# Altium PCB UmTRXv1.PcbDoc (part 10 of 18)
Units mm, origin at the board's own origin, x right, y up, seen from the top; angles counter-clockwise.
Board outline 172 x 113 mm, 6 copper layers (Top Layer, GND, MidLayer1, Mid-Layer 2, InternalPlane2, Bottom Layer); 766 components, 613 nets, 3008 pads, 1360 vias.
Unrouted connection lines stored in the file: 2.
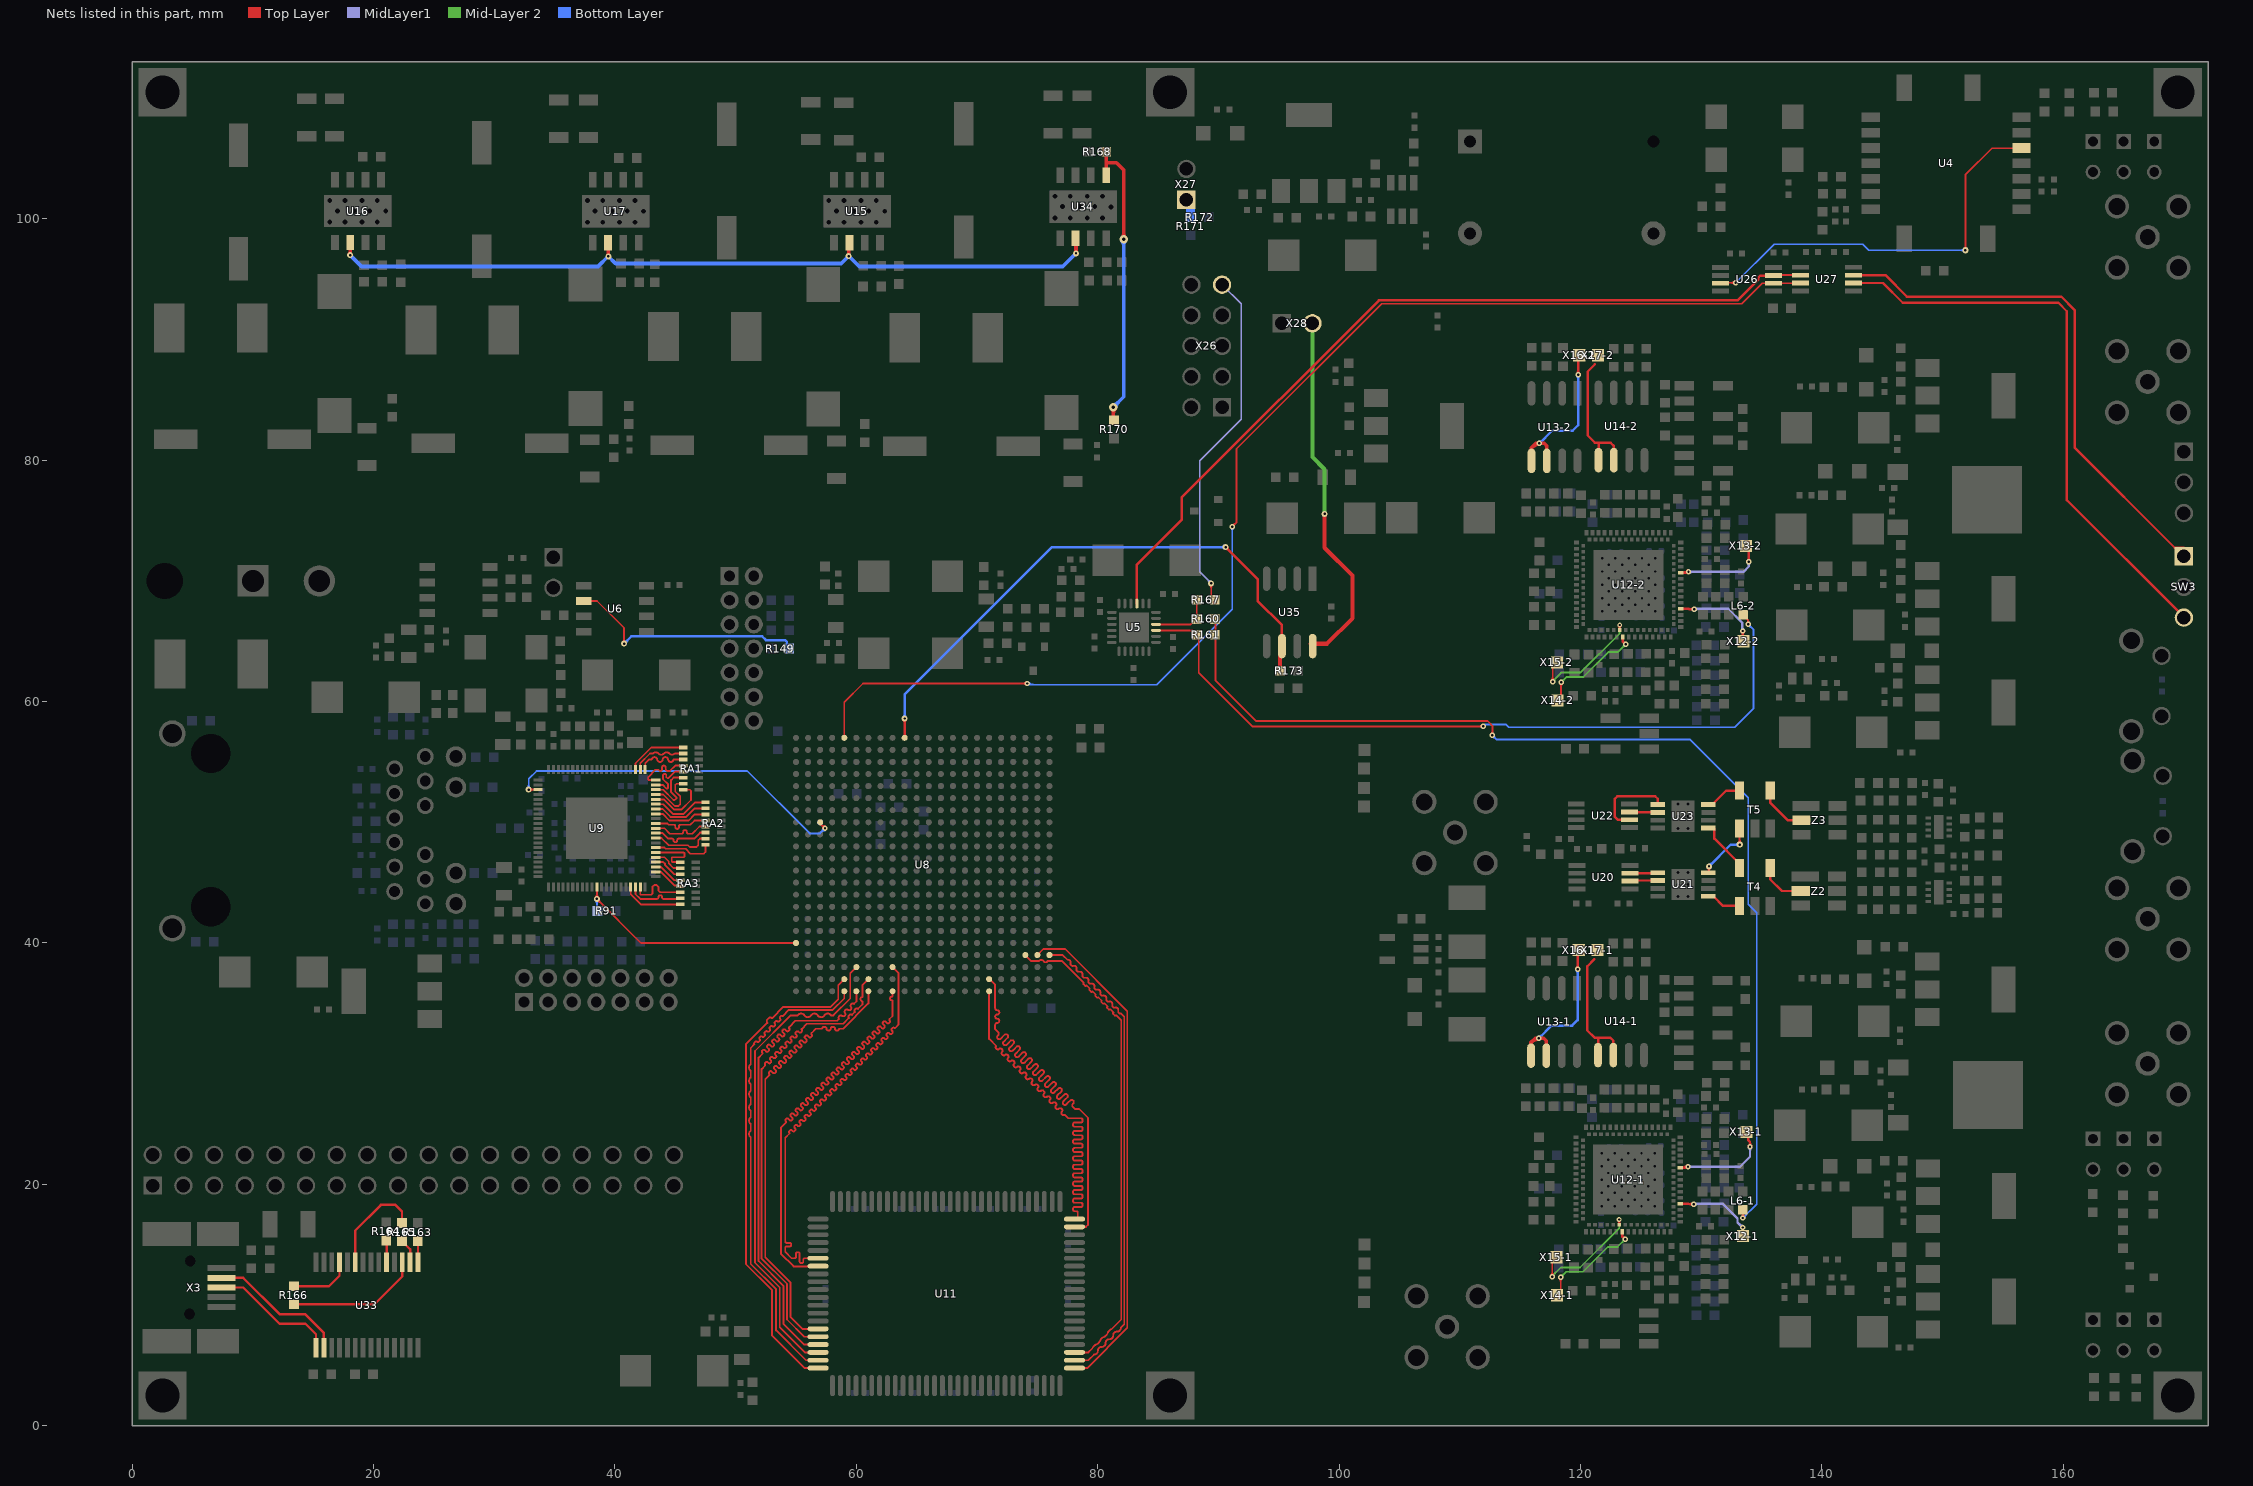
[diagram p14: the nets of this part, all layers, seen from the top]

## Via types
v1: diameter 0.45, hole 0.2, Top Layer to Bottom Layer, tented both sides, 554 vias
v2: diameter 0.5, hole 0.2, Top Layer to Bottom Layer, tented both sides, 468 vias
v3: diameter 0.7, hole 0.3, Top Layer to Bottom Layer, tented both sides, 206 vias
v4: diameter 0.4, hole 0.2, Top Layer to Bottom Layer, tented both sides, 82 vias
v5: diameter 0.8, hole 0.3, Top Layer to Bottom Layer, tented both sides, 16 vias
v6: diameter 0.6, hole 0.25, Top Layer to Bottom Layer, tented both sides, 16 vias
v7: diameter 0.5, hole 0.3, Top Layer to Bottom Layer, tented both sides, 8 vias
v8: diameter 0.7, hole 0.3, Top Layer to Bottom Layer, 4 vias
v9: diameter 0.6, hole 0.3, Top Layer to Bottom Layer, tented both sides, 4 vias
v10: diameter 0.5, hole 0.2, Top Layer to Bottom Layer, 2 vias

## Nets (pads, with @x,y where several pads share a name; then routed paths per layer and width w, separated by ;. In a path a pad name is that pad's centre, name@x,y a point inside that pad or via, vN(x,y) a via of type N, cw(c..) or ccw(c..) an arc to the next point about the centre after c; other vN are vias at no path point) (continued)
NetR149_2: R149.2 U6.2 | length 21.3
  Top Layer w0.15: U6.2@37.401,68.339 38.511,68.339 40.75,66.1 v2(40.75,64.8) ; v2@40.626,64.924 ccw(c40.328,65.222) 40.75,65.222 ccw(c41.172,65.222) v2@40.874,64.924
  Bottom Layer w0.2: v2(40.75,64.8) 41.35,65.4 52.2,65.4 52.5,65.1 54.1,65.1 54.25,64.95 R149.2@54.25,64.4 ; v2@40.75,64.95 ccw(c40.75,65.312) 41.006,65.056 ccw(c41.262,64.8) v2@40.9,64.8
NetR160_1: R160.1 R167.1 U5.22 | length 5.1
  Top Layer w0.15: U5.22@84.825,66.4 87.7,66.4 88.2,66.9 R167.1@88.2,68.45
NetR163_2: R163.2 U33.1 | length 1.8
  Top Layer w0.2: R163.2@23.65,15.3 23.675,15.275 U33.1@23.675,13.55
NetR164_2: R164.2 U33.5 | length 1.8
  Top Layer w0.2: R164.2@21.05,15.35 21.075,15.325 U33.5@21.075,13.55
NetR165_1: R165.1 U33.2 | length 2
  Top Layer w0.2: R165.1@22.35,15.3 23.025,14.625 U33.2@23.025,13.55
NetR165_2: R165.2 U33.9 | length 8.6
  Top Layer w0.2: U33.9@18.475,13.55 18.475,16.175 20.6,18.3 21.8,18.3 22.35,17.75 R165.2@22.35,16.8
NetR166_1: R166.1 U33.3 | length 11.1
  Top Layer w0.2: R166.1@13.4,10.05 20.05,10.05 22.375,12.375 U33.3@22.375,13.55
NetR166_2: R166.2 U33.11 | length 5.3
  Top Layer w0.2: R166.2@13.4,11.55 16.3,11.55 17.175,12.425 U33.11@17.175,13.55
NetR168_2: R168.2 R170.2 U34.5 | length 27.8
  Top Layer w0.3: U34.5@80.703,103.602 80.703,104.65 ; R168.2@80.703,105.547 80.703,104.65 ; v3@81.159,84.259 cw(c80.817,83.917) 81.3,83.917 cw(c81.783,83.917) v3@81.441,84.259 ; v3(81.3,84.4) 81.3,83.35 R170.2@81.35,83.3 ; v3@82.009,98.441 ccw(c81.667,98.783) 82.15,98.783 ccw(c82.633,98.783) v3@82.291,98.441 ; v3(82.15,98.3) 82.15,104.05 81.55,104.65 80.703,104.65
  Bottom Layer w0.3: v3(81.3,84.4) 82.15,85.25 v3(82.15,98.3) ; v3@81.3,84.6 ccw(c81.3,85.083) 81.641,84.741 ccw(c81.983,84.4) v3@81.5,84.4 ; v3@82.009,98.159 cw(c81.667,97.817) 82.15,97.817 cw(c82.633,97.817) v3@82.291,98.159
NetR171_2: R171.2 R172.2 X27.1 | length 1.6
  Bottom Layer w0.75: X27.1@87.35,101.6 87.7,101.25 R172.2@87.7,100.15
NetRA1_1: RA1.1 U9.3 | length 5
  Top Layer w0.15: U9.3@41.7,54.375 41.7,54.9 43,56.2 RA1.1@45.65,56.2
NetRA1_2: RA1.2 U9.2 | length 4.6
  Top Layer w0.15: U9.2@42.1,54.375 42.1,54.9 42.9,55.7 43.15,55.7 cw(c43.375,55.497) 43.6,55.7 ccw(c43.825,55.903) 44.05,55.7 cw(c44.275,55.497) 44.5,55.7 ccw(c44.725,55.903) 44.95,55.7 RA1.2@45.65,55.7
NetRA1_3: RA1.3 U9.1 | length 4.6
  Top Layer w0.15: U9.1@42.5,54.375 42.5,54.9 42.8,55.2 43.05,55.2 cw(c43.275,55.173) 43.5,55.2 ccw(c43.725,55.227) 43.95,55.2 cw(c44.175,55.173) 44.4,55.2 ccw(c44.625,55.227) 44.85,55.2 RA1.3@45.65,55.2
NetRA1_4: RA1.4 U9.84 | length 4.9
  Top Layer w0.15: U9.84@43.375,53.5 42.8,53.5 42.75,53.55 42.75,53.75 43.35,54.35 43.604,54.35 43.704,54.25 43.75,54.25 ccw(c43.75,54.4) 43.9,54.4 43.9,54.547 cw(c44.05,54.547) 44.05,54.697 cw(c44.05,54.547) 44.2,54.547 44.2,54.4 ccw(c44.35,54.4) 44.35,54.25 44.55,54.25 45,54.7 RA1.4@45.65,54.7
NetRA1_5: RA1.5 U9.83 | length 4.6
  Top Layer w0.15: U9.83@43.375,53.1 43.95,53.1 44.25,52.8 44.35,52.8 44.4,52.85 44.4,53.15 43.975,53.575 43.975,53.925 44.05,54 44.2,54 44.25,53.95 44.25,53.75 44.35,53.65 44.4,53.65 44.95,54.2 RA1.5@45.65,54.2
NetRA1_6: RA1.6 U9.82 | length 4.9
  Top Layer w0.15: U9.82@43.375,52.7 43.996,52.7 44.846,51.85 44.95,51.85 45.1,52 45.1,52.05 44.65,52.5 44.65,53.5 44.85,53.7 RA1.6@45.65,53.7
NetRA1_7: RA1.7 U9.81 | length 4.9
  Top Layer w0.15: U9.81@43.375,52.3 44.004,52.3 44.954,51.35 45.25,51.35 45.4,51.5 45.4,52.15 45,52.55 45,53.1 45.1,53.2 RA1.7@45.65,53.2
NetRA1_8: RA1.8 U9.80 | length 5
  Top Layer w0.15: U9.80@43.375,51.9 44.05,51.9 44.9,51.05 45.5,51.05 46.3,51.85 46.3,52.6 46.2,52.7 RA1.8@45.65,52.7
NetRA2_1: RA2.1 U9.79 | length 4.8
  Top Layer w0.15: U9.79@43.375,51.5 44,51.5 44.8,50.7 45.7,50.7 46.65,51.65 RA2.1@47.5,51.65
NetRA2_2: RA2.2 U9.78 | length 4.7
  Top Layer w0.15: U9.78@43.375,51.1 43.95,51.1 44.6,50.45 45.9,50.45 46.6,51.15 RA2.2@47.5,51.15
NetRA2_3: RA2.3 U9.77 | length 4.6
  Top Layer w0.15: U9.77@43.375,50.7 43.95,50.7 44.5,50.15 46.1,50.15 46.6,50.65 RA2.3@47.5,50.65
NetRA2_4: RA2.4 U9.75 | length 4.8
  Top Layer w0.15: U9.75@43.375,49.9 44.35,49.9 44.45,49.8 44.865,49.8 cw(c44.865,49.665) 45,49.665 45,49.587 ccw(c45.135,49.587) 45.135,49.452 45.165,49.452 ccw(c45.165,49.587) 45.3,49.587 45.3,49.665 cw(c45.435,49.665) 45.435,49.8 46.25,49.8 46.6,50.15 RA2.4@47.5,50.15
NetRA2_5: RA2.5 U9.74 | length 4.9
  Top Layer w0.15: U9.74@43.375,49.5 44.1,49.5 44.55,49.05 45.515,49.05 ccw(c45.515,49.185) 45.65,49.185 45.65,49.215 cw(c45.785,49.215) 45.785,49.35 45.815,49.35 cw(c45.815,49.215) 45.95,49.215 45.95,49.185 ccw(c46.085,49.185) 46.085,49.05 46.4,49.05 47,49.65 RA2.5@47.5,49.65
NetRA2_6: RA2.6 U9.73 | length 4.9
  Top Layer w0.15: U9.73@43.375,49.1 43.95,49.1 44.4,48.65 44.715,48.65 cw(c44.715,48.515) 44.85,48.515 44.85,48.485 ccw(c44.985,48.485) 44.985,48.35 45.015,48.35 ccw(c45.015,48.485) 45.15,48.485 45.15,48.515 cw(c45.285,48.515) 45.285,48.65 46.55,48.65 47.05,49.15 RA2.6@47.5,49.15
NetRA2_7: RA2.7 U9.72 | length 5
  Top Layer w0.15: U9.72@43.375,48.7 43.85,48.7 44.45,48.1 46.05,48.1 46.2,47.95 46.75,47.95 46.9,48.1 46.9,48.5 47.05,48.65 RA2.7@47.5,48.65
NetRA2_8: RA2.8 U9.70 | length 5
  Top Layer w0.15: U9.70@43.375,47.9 44.1,47.9 44.2,47.8 45.85,47.8 46.25,47.4 47.35,47.4 47.5,47.55 RA2.8@47.5,48.15
NetRA3_1: RA3.1 U9.69 | length 4.8
  Top Layer w0.15: U9.69@43.375,47.5 45.7,47.5 45.75,47.45 45.75,47.15 45.7,47.1 44.75,47.1 44.7,47.05 44.7,46.75 44.75,46.7 RA3.1@45.4,46.7
NetRA3_2: RA3.2 U9.68 | length 2.5
  Top Layer w0.15: U9.68@43.375,47.1 44.1,47.1 44.45,46.75 44.45,46.6 44.85,46.2 RA3.2@45.4,46.2
NetRA3_3: RA3.3 U9.67 | length 2.5
  Top Layer w0.15: U9.67@43.375,46.7 44,46.7 44.15,46.55 44.15,46.45 44.9,45.7 RA3.3@45.4,45.7
NetRA3_4: RA3.4 U9.66 | length 2.5
  Top Layer w0.15: U9.66@43.375,46.3 43.8,46.3 44.9,45.2 RA3.4@45.4,45.2
NetRA3_5: RA3.5 U9.65 | length 2.5
  Top Layer w0.15: U9.65@43.375,45.9 43.8,45.9 44.95,44.75 RA3.5@45.35,44.75
NetRA3_6: RA3.6 U9.62 | length 5
  Top Layer w0.15: U9.62@42.1,44.625 42.1,44.05 42.15,44 43,44 43.1,44.1 43.1,44.65 43.25,44.8 43.446,44.8 43.5,44.746 43.5,44.743 43.6,44.643 43.6,44.35 43.75,44.2 RA3.6@45.4,44.2
NetRA3_7: RA3.7 U9.61 | length 4.8
  Top Layer w0.15: U9.61@41.7,44.625 41.7,44.05 42.1,43.65 43.465,43.65 ccw(c43.465,43.785) 43.6,43.785 43.6,43.815 cw(c43.735,43.815) 43.735,43.95 43.765,43.95 cw(c43.765,43.815) 43.9,43.815 43.9,43.785 ccw(c44.035,43.785) 44.035,43.65 45.35,43.65 RA3.7@45.4,43.7
NetRA3_8: RA3.8 U9.60 | length 5
  Top Layer w0.15: U9.60@41.3,44.625 41.3,44.05 42.15,43.2 RA3.8@45.4,43.2
NetSW3_1: SW3.1 U27.7 | length 43.4
  Top Layer w0.2: U27.7@142.621,95.336 145.264,95.336 147.05,93.55 159.85,93.55 160.95,92.45 160.95,81.05 169.25,72.75 SW3.1@170,72.75
NetSW3_3: SW3.3 U27.6 | length 48.3
  Top Layer w0.2: U27.6@142.621,94.686 145.064,94.686 146.7,93.05 159.6,93.05 160.3,92.35 160.3,76.7 170,67 SW3.3@170.3,67
NetT4_3: T4.3 U21.5 | length 2.9
  Top Layer w0.2: U21.5@130.6,43.875 131.025,43.875 131.825,43.075 T4.3@133.18,43.075
NetT4_4: T4.4 U23.5 | length 4.6
  Top Layer w0.2: U23.5@130.6,49.525 131.025,49.525 131.1,49.45 131.1,48.65 133.18,46.57 T4.4@133.18,46.225
NetT4_6: T4.6 Z2.2 | length 4.2
  Top Layer w0.2: T4.6@135.72,46.225 135.72,45.28 136.694,44.306 Z2.2@138.251,44.306 Z2.2@138.046,44.1
NetT5_3: T5.3 U21.8 | length 7.4
  Top Layer w0.2: v2@130.544,46.244 cw(c130.288,45.988) 130.65,45.988 cw(c131.012,45.988) v2@130.756,46.244 ; U21.8@130.6,45.825 130.65,45.875 v2(130.65,46.35) ; v2@133.094,48.256 ccw(c132.886,48.464) 133.18,48.464 ; 133.18,48.56 ccw(c133.61,48.56) v2@133.306,48.256 ; T5.3@133.18,49.475 133.18,48.17 v2(133.2,48.15)
  Bottom Layer w0.2: v2(130.65,46.35) 132.45,48.15 v2(133.2,48.15) ; v2@130.65,46.5 ccw(c130.65,46.862) 130.906,46.606 ccw(c131.162,46.35) v2@130.8,46.35 ; v2@133.094,48.044 ccw(c132.838,47.788) 132.838,48.15 ccw(c132.838,48.512) v2@133.094,48.256
NetT5_4: T5.4 U23.8 | length 3.1
  Top Layer w0.2: U23.8@130.6,51.475 130.925,51.475 132.075,52.625 T5.4@133.18,52.625
NetT5_6: T5.6 Z3.2 | length 4.2
  Top Layer w0.2: T5.6@135.72,52.625 135.72,51.63 137.194,50.156 Z3.2@138.301,50.156
NetU4_5: U4.5 U26.3 | length 36.1
  Top Layer w0.15: U26.3@131.608,94.671 131.637,94.7 v1(132.85,94.7) ; v1@132.744,94.594 ccw(c132.488,94.338) 132.488,94.7 ccw(c132.488,95.062) v1@132.744,94.806 ; v2@151.776,97.524 ccw(c151.478,97.822) 151.9,97.822 ccw(c152.322,97.822) v2@152.024,97.524 ; v2(151.9,97.4) 151.9,103.65 154.1,105.85 U4.5@156.55,105.85
  Bottom Layer w0.15: v1(132.85,94.7) 136.05,97.9 143.4,97.9 143.9,97.4 v2(151.9,97.4) ; v1@132.85,94.85 ccw(c132.85,95.212) 133.106,94.956 ccw(c133.362,94.7) v1@133,94.7 ; v2@151.776,97.276 ccw(c151.478,96.978) 151.478,97.4 ccw(c151.478,97.822) v2@151.776,97.524
NetU5_3: U5.3 U26.7 U27.2 | length 69.2
  Top Layer w0.15: U26.7@135.978,95.35 138.207,95.35 U27.2@138.221,95.336
  Top Layer w0.2: U5.3@83.25,68.125 83.25,71.35 86.95,75.05 86.95,76.9 103.3,93.25 133.024,93.25 134.75,94.976 134.75,95.15 134.9,95.3 U26.7@135.85,95.3 ; U26.7@135.978,95.35 U26.7@136.008,95.321
NetU12-1_41: U12-1.41 X15-1.1 | length 12.1
  Top Layer w0.15: v1@117.555,12.464 ccw(c117.299,12.72) 117.661,12.72 ccw(c118.023,12.72) v1@117.767,12.464 ; v1(117.661,12.358) 117.661,13.608 X15-1.1@118.011,13.958
  Top Layer w0.2: v4@123.136,17.017 cw(c122.966,16.847) 123.207,16.847 cw(c123.448,16.847) v4@123.278,17.017 ; U12-1.41@123.207,16.638 v4@123.207,17.063
  Mid-Layer 2 w0.15: v1(117.661,12.358) 117.661,12.408 118.361,13.108 119.961,13.108 123.207,16.354 v4(123.207,17.088) ; v1@117.661,12.508 ccw(c117.661,12.75) 117.832,12.579 ; v1@117.811,12.358 cw(c118.294,12.358) 117.952,12.7 ; v4@123.119,17 cw(c122.905,16.786) 123.207,16.786 cw(c123.509,16.786) v4@123.295,17
NetU12-1_42: U12-1.42 X14-1.1 | length 11
  Top Layer w0.15: X14-1.1@118.061,10.808 118.361,11.108 v1(118.361,12.308) ; v1@118.255,12.202 cw(c117.999,11.946) 118.361,11.946 cw(c118.723,11.946) v1@118.467,12.202
  Top Layer w0.2: U12-1.42@123.457,16.063 123.457,15.662 ; v1@123.694,15.582 cw(c123.657,15.862) 123.457,15.662 ; v1(123.711,15.458) 123.661,15.458 123.457,15.662
  Mid-Layer 2 w0.15: v1(118.361,12.308) 118.811,12.758 120.211,12.758 122.261,14.808 123.061,14.808 v1(123.711,15.458) ; v1@118.361,12.458 ccw(c118.361,12.82) 118.617,12.564 ccw(c118.873,12.308) v1@118.511,12.308 ; v1@123.561,15.458 cw(c123.199,15.458) 123.455,15.202 cw(c123.711,14.946) v1@123.711,15.308
NetU12-1_65: U12-1.65 X12-1.1 | length 7.6
  Top Layer w0.2: U12-1.65@128.282,18.388 128.941,18.388 128.961,18.368 129.386,18.368 v1(129.386,18.358) ; 129.062,18.368 cw(c129.062,18.034) v1@129.298,18.27 ; 129.107,18.368 ccw(c129.107,18.637) v1@129.298,18.447
  MidLayer1 w0.2: v1@129.342,18.408 131.782,18.408 133.016,17.174 133.016,16.852 v1@133.461,16.407 ; v1@129.474,18.27 cw(c129.809,17.936) 129.809,18.408 ; v1@133.318,16.425 ccw(c133.016,16.425) 133.23,16.638 ccw(c133.443,16.851) v1@133.443,16.55
  other v1: 133.443,16.425
NetU12-1_77: U12-1.77 X13-1.1 | length 10.1
  Top Layer w0.2: U12-1.77@128.282,21.388 128.841,21.388 v1(128.911,21.458) ; U12-1.77@128.44,21.388 ccw(c128.44,21.929) v1@128.823,21.547 ; X13-1.1@133.911,24.35 133.911,23.639 134.05,23.5 v1(134.05,23.1) ; v1@133.962,23.188 ccw(c133.748,23.402) 134.05,23.402 ccw(c134.352,23.402) v1@134.138,23.188
  MidLayer1 w0.2: v1(128.911,21.458) 133.22,21.458 134.05,22.288 v1(134.05,23.1) ; v1@128.999,21.37 cw(c129.213,21.156) 129.213,21.458 cw(c129.213,21.76) v1@128.999,21.547 ; v1@133.962,23.012 cw(c133.748,22.798) 134.05,22.798 cw(c134.352,22.798) v1@134.138,23.012
NetU12-2_41: U12-2.41 X15-2.1 | length 12.2
  Top Layer w0.15: v1@117.594,61.756 ccw(c117.338,62.012) 117.7,62.012 ccw(c118.062,62.012) v1@117.806,61.756 ; v1(117.7,61.65) 117.7,62.9 X15-2.1@118.05,63.25 ; v4@123.162,66.262 cw(c122.948,66.048) 123.25,66.048 cw(c123.552,66.048) v4@123.338,66.262 ; U12-2.41@123.246,65.93 123.25,65.934 v4(123.25,66.35)
  Mid-Layer 2 w0.15: v1(117.7,61.65) 117.7,61.7 118.4,62.4 120,62.4 123.246,65.646 v4@123.246,66.38 ; v1@117.7,61.8 ccw(c117.7,62.041) 117.871,61.871 ; v1@117.85,61.65 cw(c118.333,61.65) 117.991,61.991 ; v4@123.162,66.262 cw(c122.958,66.058) 123.246,66.058 ; 123.246,66.038 cw(c123.562,66.038) v4@123.338,66.262
NetU12-2_42: U12-2.42 X14-2.1 | length 11
  Top Layer w0.15: X14-2.1@118.1,60.1 118.4,60.4 v1(118.4,61.6) ; v1@118.294,61.494 cw(c118.038,61.238) 118.4,61.238 cw(c118.762,61.238) v1@118.506,61.494
  Top Layer w0.2: U12-2.42@123.496,65.355 123.496,64.954 ; v1@123.733,64.874 cw(c123.696,65.154) 123.496,64.954 ; v1(123.75,64.75) 123.7,64.75 123.496,64.954
  Mid-Layer 2 w0.15: v1(118.4,61.6) 118.85,62.05 120.25,62.05 122.3,64.1 123.1,64.1 v1(123.75,64.75) ; v1@118.4,61.75 ccw(c118.4,62.112) 118.656,61.856 ccw(c118.912,61.6) v1@118.55,61.6 ; v1@123.6,64.75 cw(c123.238,64.75) 123.494,64.494 cw(c123.75,64.238) v1@123.75,64.6
NetU12-2_65: U12-2.65 X12-2.1 | length 8.9
  Top Layer w0.2: U12-2.65@128.321,67.68 128.98,67.68 129,67.659 129.425,67.659 v1(129.425,67.65) ; 129.101,67.659 cw(c129.101,67.326) v1@129.337,67.562 ; 129.146,67.659 ccw(c129.146,67.929) v1@129.337,67.738 ; v1@133.362,65.762 cw(c133.148,65.548) 133.45,65.548 cw(c133.752,65.548) v1@133.538,65.762 ; v1(133.45,65.85) 133.45,65.05 X12-2.1@133.5,65
  MidLayer1 w0.2: v1@129.381,67.7 132.25,67.7 133.4,66.55 v1@133.4,65.799 ; v1@129.513,67.562 cw(c129.847,67.228) 129.847,67.7 ; 133.4,66.272 ccw(c133.872,66.272) v1@133.538,65.938
NetU12-2_77: U12-2.77 X13-2.1 | length 9.3
  Top Layer w0.2: U12-2.77@128.321,70.68 128.88,70.68 v1(128.95,70.75) ; U12-2.77@128.479,70.68 ccw(c128.479,71.221) v1@128.862,70.838 ; X13-2.1@133.7,72.9 133.95,72.65 v1(133.95,71.6) ; v1@133.862,71.688 ccw(c133.648,71.902) 133.95,71.902 ccw(c134.252,71.902) v1@134.038,71.688
  MidLayer1 w0.2: v1(128.95,70.75) 133.5,70.75 133.95,71.2 v1@133.95,71.441 ; v1@129.038,70.662 cw(c129.252,70.448) 129.252,70.75 cw(c129.252,71.052) v1@129.038,70.838 ; v1@133.862,71.512 cw(c133.648,71.298) 133.95,71.298 cw(c134.252,71.298) v1@134.038,71.512
NetU13-1_5: U13-1.5 U13-1.6 X16-1.1 | length 15.6
  Top Layer w0.2: v1@119.673,37.897 ccw(c119.459,38.11) 119.761,38.11 ccw(c120.063,38.11) v1@119.849,37.897 ; v1(119.761,37.808) 119.761,39.308 X16-1.1@119.861,39.408
  Top Layer w0.3: U13-1.5@115.906,30.661 115.906,31.753 116.261,32.108 v1(116.561,32.108) 116.961,32.108 117.176,31.893 U13-1.6@117.176,30.661 ; 115.921,31.768 cw(c116.561,31.128) v1@116.561,32.033
  Bottom Layer w0.2: v1(116.561,32.108) 117.611,33.158 119.311,33.158 119.761,33.608 v1(119.761,37.808) ; v1@116.561,32.233 ccw(c116.561,32.535) 116.774,32.322 ccw(c116.988,32.108) v1@116.686,32.108 ; v1@119.673,37.72 cw(c119.459,37.506) 119.761,37.506 cw(c120.063,37.506) v1@119.849,37.72
NetU13-2_5: U13-2.5 U13-2.6 X16-2.1 | length 15.6
  Top Layer w0.2: v1@119.712,87.188 ccw(c119.498,87.402) 119.8,87.402 ccw(c120.102,87.402) v1@119.888,87.188 ; v1(119.8,87.1) 119.8,88.6 X16-2.1@119.9,88.7
  Top Layer w0.3: U13-2.5@115.945,79.953 115.945,81.045 116.3,81.4 v1(116.6,81.4) 117,81.4 117.215,81.185 U13-2.6@117.215,79.953 ; 115.96,81.06 cw(c116.6,80.42) v1@116.6,81.325
  Bottom Layer w0.2: v1(116.6,81.4) 117.65,82.45 119.35,82.45 119.8,82.9 v1(119.8,87.1) ; v1@116.6,81.525 ccw(c116.6,81.827) 116.813,81.613 ccw(c117.027,81.4) v1@116.725,81.4 ; v1@119.712,87.012 cw(c119.498,86.798) 119.8,86.798 cw(c120.102,86.798) v1@119.888,87.012
NetU14-1_5: U14-1.5 U14-1.6 X17-1.1 | length 11.3
  Top Layer w0.2: 121.161,38.658 120.561,38.058 120.561,32.758 121.161,32.158 121.461,32.158 ; U14-1.5@121.456,30.711 121.461,30.716 121.461,32.158 ; U14-1.6@122.726,30.711 122.726,31.893 122.461,32.158 121.461,32.158
NetU14-2_5: U14-2.5 U14-2.6 X17-2.1 | length 11.3
  Top Layer w0.2: 121.2,87.95 120.6,87.35 120.6,82.05 121.2,81.45 121.5,81.45 ; U14-2.5@121.495,80.003 121.5,80.008 121.5,81.45 ; U14-2.6@122.765,80.003 122.765,81.185 122.5,81.45 121.5,81.45
NetU15_2: U15.2 U16.2 U17.2 U34.2 | length 67
  Top Layer w0.3: v2@17.979,97.071 ccw(c17.777,97.273) 18.063,97.273 ; v2(18.05,97) 18.063,97.013 U16.2@18.063,98.042 ; U17.2@39.423,98.029 39.45,98.002 v2(39.45,96.9) ; v2(59.365,96.918) 59.365,97.971 U15.2@59.423,98.029 ; U34.2@78.163,98.392 78.2,98.355 v2(78.2,97.15)
  Bottom Layer w0.3: v2(18.05,97) 19,96.05 38.6,96.05 v2(39.45,96.9) 40.05,96.3 58.747,96.3 v2(59.365,96.918) 60.233,96.05 77.1,96.05 v2(78.2,97.15)
NetU20_2: U20.2 U21.2 | length 2.3
  Top Layer w0.2: U20.2@124.101,45.131 124.146,45.175 U21.2@126.4,45.175
NetU20_3: U20.3 U21.1 | length 2.3
  Top Layer w0.2: U20.3@124.101,45.781 126.356,45.781 U21.1@126.4,45.825
NetU22_2: U22.2 U23.1 | length 7.1
  Top Layer w0.2: U22.2@124.07,50.225 U22.2@124.051,50.206 123.106,50.206 123.1,50.2 122.85,50.45 122.85,51.95 123.05,52.15 126.2,52.15 126.4,51.95 U23.1@126.4,51.475 ; U23.1@126.431,51.456 U23.1@126.45,51.475
NetU22_3: U22.3 U23.2 | length 2.4
  Top Layer w0.2: U22.3@124.051,50.856 124.082,50.825 U23.2@126.4,50.825
NetU33_15: U33.15 X3.3 | length 10.6
  Top Layer w0.2: X3.3@7.4,11.45 9.2,11.45 12.2,8.45 14.35,8.45 15.225,7.575 U33.15@15.225,6.45
NetU33_16: U33.16 X3.2 | length 11.6
  Top Layer w0.2: X3.2@7.4,12.25 9.2,12.25 12.2,9.25 14.3,9.25 15.875,7.675 U33.16@15.875,6.45
NetU35_8: U35.8 X28.2 | length 30.1
  Top Layer w0.35: U35.8@97.65,64.8 99,64.8 101.1,66.9 101.1,70.45 98.8,72.75 v2(98.8,75.55)
  Mid-Layer 2 w0.35: X28.2@97.79,91.35 97.79,80.26 98.8,79.25 v2(98.8,75.55)
OVERHEAT: R173.2 U8.AB13 U35.6 | length 49.5
  Top Layer w0.2: v2@63.894,58.494 cw(c63.638,58.238) 64,58.238 cw(c64.362,58.238) v2@64.106,58.494 ; U8.AB13@64,57 v2(64,58.6) ; v2@90.6,72.65 cw(c90.6,72.288) 90.856,72.544 cw(c91.112,72.8) v2@90.75,72.8 ; v2(90.6,72.8) 93.25,70.15 93.25,68.35 95.265,66.335 U35.6@95.265,64.603
  Top Layer w0.35: R173.2@95.1,62.55 U35.6@95.1,64.438
  Bottom Layer w0.2: v2@63.894,58.706 ccw(c63.638,58.962) 64,58.962 ccw(c64.362,58.962) v2@64.106,58.706 ; v2(64,58.6) 64,60.6 76.2,72.8 v2(90.6,72.8) ; v2@90.494,72.694 ccw(c90.238,72.438) 90.238,72.8 ccw(c90.238,73.162) v2@90.494,72.906
PHY_INTN: R91.2 U8.E22 U9.53 | length 22
  Top Layer w0.15: v2@38.376,43.774 ccw(c38.078,44.072) 38.5,44.072 ccw(c38.922,44.072) v2@38.624,43.774 ; v2@38.5,43.475 cw(c38.5,43.053) 38.799,43.351 cw(c39.097,43.65) v2@38.675,43.65 ; U9.53@38.5,44.625 v2(38.5,43.65) 42.15,40 U8.E22@55,40
  Bottom Layer w0.15: v2@38.376,43.526 cw(c38.078,43.228) 38.5,43.228 cw(c38.922,43.228) v2@38.624,43.526 ; R91.2@38.5,42.65 v2(38.5,43.65)
PHY_RESETN: U8.R20 U9.24 | length 32.2
  Top Layer w0.15: v2(32.85,52.7) 32.85,52.65 32.9,52.7 U9.24@33.625,52.7 ; v2@32.974,52.576 cw(c33.272,52.278) 33.272,52.7 cw(c33.273,53.123) v2@32.974,52.824 ; U8.R20@57,50 57,49.9 v1(57.4,49.5) ; v1@57.225,49.5 ccw(c56.803,49.5) 57.101,49.799 ccw(c57.4,50.097) v1@57.4,49.675
  Bottom Layer w0.15: v2@32.726,52.824 ccw(c32.428,53.122) 32.85,53.122 ccw(c33.272,53.122) v2@32.974,52.824 ; v2(32.85,52.7) 32.85,53.6 33.5,54.25 50.95,54.25 56.125,49.075 56.975,49.075 v1(57.4,49.5) ; v1@57.225,49.5 cw(c56.803,49.5) 57.101,49.201 cw(c57.4,48.903) v1@57.4,49.325
PLL0CLK: R167.2 X26.9 | length 30
  Top Layer w0.15: v2@89.276,69.676 cw(c88.978,69.378) 89.4,69.378 cw(c89.822,69.378) v2@89.524,69.676 ; v2(89.4,69.8) 89.4,68.75 R167.2@89.7,68.45
  MidLayer1 w0.15: v2@89.225,69.8 ccw(c88.803,69.8) 89.101,70.099 ccw(c89.4,70.397) v2@89.4,69.975 ; v2(89.4,69.8) 88.45,70.75 88.45,79.95 91.9,83.4 91.9,92.95 X26.9@90.3,94.55
PLL1CLK: L6-1.1 R160.2 R161.1 | length 92.4
  Top Layer w0.15: R160.2@89.763,66.85 89.763,61.737 93.1,58.4 112.3,58.4 112.7,58 v1(112.7,57.2) ; v1@112.594,57.306 ccw(c112.338,57.562) 112.7,57.562 ccw(c113.062,57.562) v1@112.806,57.306 ; v1@133.355,17.314 ccw(c133.099,17.57) 133.461,17.57 ccw(c133.823,17.57) v1@133.567,17.314 ; v1(133.461,17.208) L6-1.1@133.461,17.908 L6-1.1@133.511,17.858
  Bottom Layer w0.15: v1@112.7,57.05 cw(c112.7,56.688) 112.956,56.944 cw(c113.212,57.2) v1@112.85,57.2 ; v1(112.7,57.2) 113.05,56.85 129.1,56.85 133.9,52.05 133.9,43.2 134.6,42.5 134.6,18.347 v1(133.461,17.208) ; v1@133.461,17.358 ccw(c133.461,17.72) 133.717,17.464 ccw(c133.973,17.208) v1@133.611,17.208
PLL2CLK: L6-2.1 R161.2 U5.21 | length 65
  Top Layer w0.15: U5.21@84.825,65.9 87.85,65.9 R161.2@88.2,65.55 88.367,65.383 88.367,62.383 92.8,57.95 v1(111.95,57.95) v1@112,57.9 ; v1@111.844,57.844 ccw(c111.588,57.588) 111.588,57.95 ccw(c111.588,58.312) v1@111.844,58.056 ; L6-2.1@133.5,67.2 L6-2.1@133.55,67.15 ; L6-2.1@133.7,66.95 133.9,66.75 ; v1@133.797,66.509 ccw(c133.567,66.75) 133.9,66.75 ; v1(133.9,66.4) 133.9,66.75 ; v1@134.003,66.509 cw(c134.233,66.75) 133.9,66.75
  Bottom Layer w0.15: v1(111.95,57.95) 112.1,58.1 113.85,58.1 114.075,57.875 132.775,57.875 134.35,59.45 134.35,65.95 v1(133.9,66.4) ; v1@133.9,66.25 cw(c133.9,65.888) 134.156,66.144 cw(c134.412,66.4) v1@134.05,66.4
PPS_IN: U8.AB18 U26.6 U27.3 | length 106.8
  Top Layer w0.15: U8.AB18@59,57 59,59.95 60.55,61.5 v1(74.15,61.5) ; v1@74.044,61.394 ccw(c73.788,61.138) 73.788,61.5 ccw(c73.788,61.862) v1@74.044,61.606 ; v1(91.15,74.5) 91.5,74.85 91.5,80.948 103.527,92.975 133.354,92.975 135.05,94.671 U26.6@136.008,94.671 138.205,94.671 U27.3@138.221,94.686 ; v1@91.15,74.65 ccw(c91.15,75.012) 91.406,74.756 ccw(c91.662,74.5) v1@91.3,74.5
  Bottom Layer w0.15: v1@74.256,61.606 ccw(c74.754,62.104) 74.754,61.4 ; 74.391,61.4 cw(c74.391,61.741) v1(74.15,61.5) 74.25,61.4 84.9,61.4 91.15,67.65 v1(91.15,74.5) ; v1@91.044,74.394 cw(c90.788,74.138) 91.15,74.138 cw(c91.512,74.138) v1@91.256,74.394
RAM_A00: U8.A14 U11.37 | length 41.2
  Top Layer w0.15: 54.361,25.425 ccw(c54.277,25.34) 54.192,25.425 54.149,25.382 ccw(c54.234,25.297) 54.149,25.213 cw(c54.093,25.156) 54.149,25.099 53.75,24.7 53.75,14.25 54.796,13.204 56.804,13.204 U11.37@56.825,13.225 ; 54.362,25.425 54.418,25.368 54.475,25.312 ccw(c54.56,25.396) 54.644,25.311 54.687,25.354 ccw(c54.602,25.439) 54.687,25.524 54.574,25.637 ; 54.574,25.637 cw(c54.659,25.722) 54.574,25.806 ; 54.574,25.807 54.616,25.849 cw(c54.701,25.764) 54.786,25.849 54.842,25.792 54.899,25.736 ccw(c54.984,25.821) 55.069,25.736 55.111,25.778 ccw(c55.026,25.863) 55.111,25.948 55.055,26.005 54.998,26.061 cw(c55.083,26.146) 54.998,26.231 55.04,26.273 cw(c55.125,26.188) 55.21,26.273 55.267,26.217 55.323,26.16 ccw(c55.408,26.245) 55.493,26.16 55.535,26.203 ccw(c55.451,26.287) 55.535,26.372 55.479,26.429 55.422,26.485 cw(c55.507,26.57) 55.422,26.655 55.465,26.698 cw(c55.55,26.613) 55.634,26.698 55.691,26.641 55.748,26.584 ccw(c55.832,26.669) 55.917,26.584 55.96,26.627 ccw(c55.875,26.712) 55.96,26.797 55.903,26.853 55.847,26.91 cw(c55.931,26.995) 55.846,27.079 ; 55.847,27.079 55.889,27.122 cw(c55.974,27.037) 56.059,27.122 56.115,27.065 56.172,27.009 ccw(c56.257,27.094) 56.341,27.009 ; 56.342,27.009 56.384,27.051 ccw(c56.299,27.136) 56.384,27.221 56.271,27.334 cw(c56.356,27.419) 56.271,27.504 56.313,27.546 cw(c56.398,27.461) 56.483,27.546 56.54,27.49 56.596,27.433 ccw(c56.681,27.518) 56.766,27.433 ; 56.766,27.433 56.808,27.475 ccw(c56.723,27.56) 56.808,27.645 56.752,27.702 56.695,27.758 cw(c56.78,27.843) 56.695,27.928 56.737,27.97 cw(c56.822,27.885) 56.907,27.97 56.964,27.914 57.02,27.857 ccw(c57.105,27.942) 57.19,27.857 57.232,27.9 ccw(c57.148,27.984) 57.233,28.069 57.176,28.126 57.119,28.182 cw(c57.204,28.267) 57.119,28.352 57.162,28.395 cw(c57.247,28.31) 57.331,28.395 57.388,28.338 57.445,28.281 ccw(c57.529,28.366) 57.614,28.281 57.657,28.324 ; 57.586,28.819 57.544,28.776 ccw(c57.628,28.692) 57.544,28.607 57.6,28.55 57.657,28.494 cw(c57.572,28.409) 57.657,28.324 ; 57.586,28.819 cw(c57.671,28.734) 57.756,28.819 57.812,28.762 57.869,28.706 ccw(c57.954,28.791) 58.038,28.706 58.081,28.748 ccw(c57.996,28.833) 58.081,28.918 58.024,28.974 57.968,29.031 cw(c58.053,29.116) 57.968,29.201 58.01,29.243 ; 58.01,29.243 cw(c58.095,29.158) 58.18,29.243 58.237,29.187 58.293,29.13 ccw(c58.378,29.215) 58.463,29.13 58.505,29.172 ccw(c58.42,29.257) 58.505,29.342 58.449,29.399 58.392,29.455 cw(c58.477,29.54) 58.392,29.625 58.435,29.667 cw(c58.519,29.583) 58.604,29.667 58.661,29.611 58.717,29.554 ccw(c58.802,29.639) 58.887,29.554 58.93,29.597 ccw(c58.845,29.682) 58.93,29.766 58.873,29.823 58.816,29.88 cw(c58.901,29.964) 58.816,30.049 58.859,30.092 ; 58.859,30.092 cw(c58.944,30.007) 59.028,30.092 ; 59.029,30.092 59.142,29.979 ccw(c59.227,30.063) 59.311,29.978 59.354,30.021 ccw(c59.269,30.106) 59.354,30.191 59.297,30.247 59.241,30.304 cw(c59.326,30.389) 59.24,30.473 59.283,30.516 cw(c59.368,30.431) 59.453,30.516 59.509,30.459 59.566,30.403 ccw(c59.651,30.488) 59.735,30.403 59.778,30.445 ; 59.778,30.445 ccw(c59.693,30.53) 59.778,30.615 59.721,30.671 59.665,30.728 cw(c59.75,30.813) 59.665,30.898 59.707,30.94 cw(c59.792,30.855) 59.877,30.94 59.934,30.884 59.99,30.827 ccw(c60.075,30.912) 60.16,30.827 60.202,30.869 ccw(c60.117,30.954) 60.202,31.039 60.146,31.096 60.089,31.152 cw(c60.174,31.237) 60.089,31.322 60.132,31.364 cw(c60.216,31.28) 60.301,31.364 60.358,31.308 60.414,31.251 ccw(c60.499,31.336) 60.584,31.251 ; 60.584,31.251 60.627,31.294 ccw(c60.542,31.379) 60.627,31.463 60.57,31.52 60.513,31.577 cw(c60.598,31.661) 60.513,31.746 60.556,31.789 cw(c60.641,31.704) 60.725,31.789 ; 60.726,31.789 60.839,31.676 ; 60.839,31.675 ccw(c60.924,31.76) 61.008,31.675 ; 60.938,32.001 cw(c61.023,32.086) 60.938,32.171 60.98,32.213 cw(c61.065,32.128) 61.15,32.213 61.206,32.156 61.263,32.1 ccw(c61.348,32.185) 61.433,32.1 61.475,32.142 ccw(c61.39,32.227) 61.475,32.312 61.419,32.369 61.362,32.425 cw(c61.447,32.51) 61.362,32.595 ; 60.938,32.001 60.994,31.944 61.051,31.888 cw(c60.966,31.803) 61.051,31.718 61.008,31.676 ; 61.362,32.595 61.404,32.637 cw(c61.489,32.552) 61.574,32.637 61.631,32.581 61.687,32.524 ccw(c61.772,32.609) 61.857,32.524 61.899,32.567 ccw(c61.815,32.651) 61.899,32.736 61.843,32.793 61.786,32.849 cw(c61.871,32.934) 61.786,33.019 61.829,33.062 cw(c61.914,32.977) 61.998,33.062 62.055,33.005 62.112,32.948 ccw(c62.196,33.033) 62.281,32.948 62.324,32.991 ccw(c62.239,33.076) 62.324,33.16 62.267,33.217 62.21,33.274 cw(c62.295,33.358) 62.21,33.443 ; 62.21,33.443 62.253,33.486 cw(c62.338,33.401) 62.423,33.486 62.479,33.429 62.536,33.373 ccw(c62.621,33.457) 62.705,33.372 62.748,33.415 ccw(c62.663,33.5) 62.748,33.585 cw(c62.804,33.641) 62.748,33.698 63,33.95 63,35.2 ccw(c62.95,35.2) 62.95,35.25 62.92,35.25 cw(c62.92,35.37) 62.8,35.37 62.8,35.43 cw(c62.92,35.43) 62.92,35.55 ccw(c62.92,35.63) 63,35.63 U8.A14@63,36
RAM_A01: U8.C14 U11.36 | length 41
  Top Layer w0.15: 55.351,24.889 55.308,24.846 cw(c55.224,24.931) 55.139,24.846 55.096,24.889 ccw(c55.011,24.804) 54.927,24.889 54.884,24.846 ccw(c54.969,24.761) 54.884,24.677 54.927,24.634 cw(c54.842,24.549) 54.927,24.465 54.884,24.422 cw(c54.799,24.507) 54.714,24.422 54.672,24.464 ccw(c54.587,24.38) 54.502,24.464 54.46,24.422 ccw(c54.545,24.337) 54.46,24.252 cw(c54.439,24.231) 54.46,24.21 54.1,23.85 54.1,15.27 ccw(c54.22,15.27) 54.22,15.15 54.48,15.15 cw(c54.48,15.03) 54.6,15.03 54.6,14.97 cw(c54.48,14.97) 54.48,14.85 54.22,14.85 ccw(c54.22,14.73) 54.1,14.73 54.1,14.4 54.625,13.875 54.88,13.875 ccw(c54.88,13.995) 55,13.995 55,14.255 cw(c55.12,14.255) 55.12,14.375 55.18,14.375 cw(c55.18,14.255) 55.3,14.255 55.3,13.595 ccw(c55.42,13.595) 55.42,13.475 55.48,13.475 ccw(c55.48,13.595) 55.6,13.595 55.6,13.755 cw(c55.72,13.755) 55.72,13.875 U11.36@56.825,13.875 ; 55.351,24.889 ccw(c55.266,24.974) 55.351,25.058 55.308,25.101 cw(c55.393,25.186) 55.308,25.27 55.351,25.313 cw(c55.436,25.228) 55.52,25.313 55.563,25.271 ccw(c55.648,25.355) 55.732,25.27 55.775,25.313 ccw(c55.69,25.398) 55.775,25.482 ; 55.775,25.483 55.754,25.504 55.733,25.525 cw(c55.817,25.61) 55.733,25.695 55.775,25.737 ; 55.775,25.737 cw(c55.86,25.652) 55.945,25.737 55.987,25.695 ccw(c56.072,25.78) 56.157,25.695 56.199,25.737 ccw(c56.114,25.822) 56.199,25.907 56.157,25.949 cw(c56.242,26.034) 56.157,26.119 56.199,26.161 cw(c56.284,26.077) 56.369,26.161 56.411,26.119 ccw(c56.496,26.204) 56.581,26.119 56.624,26.161 ccw(c56.539,26.246) 56.624,26.331 56.581,26.374 cw(c56.666,26.458) 56.581,26.543 56.624,26.586 cw(c56.708,26.501) 56.793,26.586 56.836,26.543 ccw(c56.921,26.628) 57.005,26.543 57.048,26.586 ccw(c56.963,26.671) 57.048,26.755 57.005,26.798 cw(c57.09,26.883) 57.005,26.967 ; 57.005,26.968 57.048,27.01 cw(c57.133,26.925) 57.218,27.01 57.26,26.968 ccw(c57.345,27.052) 57.43,26.967 ; 57.43,26.968 57.472,27.01 ccw(c57.387,27.095) 57.472,27.18 ; 57.472,27.18 57.451,27.201 57.43,27.222 cw(c57.515,27.307) 57.43,27.392 57.472,27.434 cw(c57.557,27.349) 57.642,27.434 57.684,27.392 ; 57.684,27.392 ccw(c57.769,27.477) 57.854,27.392 57.896,27.434 ccw(c57.812,27.519) 57.896,27.604 57.854,27.646 cw(c57.939,27.731) 57.854,27.816 57.896,27.859 cw(c57.981,27.774) 58.066,27.859 58.109,27.816 ccw(c58.193,27.901) 58.278,27.816 58.321,27.859 ccw(c58.236,27.943) 58.321,28.028 58.278,28.071 cw(c58.363,28.156) 58.278,28.24 58.321,28.283 cw(c58.405,28.198) 58.49,28.283 58.533,28.24 ccw(c58.618,28.325) 58.702,28.24 58.745,28.283 ccw(c58.66,28.368) 58.745,28.452 58.702,28.495 cw(c58.787,28.58) 58.702,28.664 ; 58.702,28.665 58.745,28.707 cw(c58.83,28.622) 58.915,28.707 58.957,28.665 ccw(c59.042,28.749) 59.127,28.664 ; 59.127,29.089 ccw(c59.212,29.004) 59.127,28.919 59.169,28.877 cw(c59.084,28.792) 59.169,28.707 59.127,28.665 ; 59.127,29.089 59.169,29.131 cw(c59.254,29.046) 59.339,29.131 59.381,29.089 ccw(c59.466,29.174) 59.551,29.089 59.593,29.131 ccw(c59.509,29.216) 59.593,29.301 59.551,29.343 cw(c59.636,29.428) 59.551,29.513 59.593,29.556 cw(c59.678,29.471) 59.763,29.556 59.806,29.513 ccw(c59.89,29.598) 59.975,29.513 60.018,29.556 ccw(c59.933,29.64) 60.018,29.725 59.975,29.768 cw(c60.06,29.853) 59.975,29.937 60.018,29.98 cw(c60.103,29.895) 60.187,29.98 ; 60.187,29.98 60.209,29.959 60.23,29.937 ccw(c60.315,30.022) 60.4,29.937 60.442,29.98 ; 60.442,29.98 ccw(c60.357,30.065) 60.442,30.15 60.4,30.192 cw(c60.484,30.277) 60.399,30.362 60.442,30.404 ; 60.442,30.404 cw(c60.527,30.319) 60.612,30.404 60.654,30.362 ccw(c60.739,30.447) 60.824,30.362 60.866,30.404 ccw(c60.781,30.489) 60.866,30.574 60.824,30.616 cw(c60.909,30.701) 60.824,30.786 60.866,30.828 cw(c60.951,30.744) 61.036,30.829 61.078,30.786 ccw(c61.163,30.871) 61.248,30.786 61.29,30.828 ccw(c61.206,30.913) 61.29,30.998 61.248,31.04 cw(c61.333,31.125) 61.248,31.21 61.29,31.253 cw(c61.375,31.168) 61.46,31.253 61.503,31.21 ccw(c61.587,31.295) 61.672,31.21 61.715,31.253 ; 61.715,31.253 ccw(c61.63,31.337) 61.715,31.422 61.672,31.465 cw(c61.757,31.55) 61.672,31.634 61.715,31.677 cw(c61.8,31.592) 61.884,31.677 61.927,31.634 ccw(c62.012,31.719) 62.096,31.634 62.139,31.677 ; 62.139,32.101 62.097,32.059 ccw(c62.181,31.974) 62.096,31.889 62.139,31.847 cw(c62.054,31.762) 62.139,31.677 ; 62.139,32.101 cw(c62.224,32.016) 62.309,32.101 62.351,32.059 ccw(c62.436,32.144) 62.521,32.059 62.563,32.101 ccw(c62.478,32.186) 62.563,32.271 62.521,32.313 cw(c62.606,32.398) 62.521,32.483 62.563,32.525 cw(c62.648,32.441) 62.733,32.526 62.775,32.483 ccw(c62.86,32.568) 62.945,32.483 62.988,32.525 ccw(c62.903,32.61) 62.988,32.695 62.966,32.716 62.945,32.738 cw(c63.03,32.822) 62.945,32.907 62.988,32.95 cw(c63.072,32.865) 63.157,32.95 ccw(c63.178,32.971) 63.2,32.95 63.5,33.25 63.5,37.5 U8.C14@63,38
RAM_A02: U8.A6 U11.100 | length 41.4
  Top Layer w0.15: U8.A6@71,36 71,32.05 71.584,31.466 ; 71.584,31.254 cw(c71.69,31.36) 71.584,31.466 ; 71.584,31.254 71.619,31.218 ; 71.62,31.218 ccw(c71.725,31.325) 71.832,31.218 cw(c71.938,31.112) 72.044,31.218 72.079,31.183 cw(c71.973,31.077) 72.079,30.971 ccw(c72.185,30.865) 72.079,30.759 72.114,30.723 ccw(c72.22,30.83) 72.327,30.723 cw(c72.433,30.617) 72.538,30.724 72.574,30.688 cw(c72.468,30.582) 72.574,30.476 ccw(c72.68,30.37) 72.574,30.264 72.609,30.229 ccw(c72.715,30.335) 72.821,30.229 cw(c72.928,30.122) 73.034,30.229 73.069,30.193 cw(c72.963,30.087) 73.069,29.981 ccw(c73.175,29.875) 73.069,29.769 73.104,29.734 ccw(c73.21,29.84) 73.316,29.734 cw(c73.423,29.627) 73.528,29.734 ; 73.529,29.734 73.564,29.698 ; 73.564,29.698 cw(c73.458,29.592) 73.564,29.486 ccw(c73.67,29.38) 73.564,29.274 73.599,29.239 ccw(c73.705,29.345) 73.811,29.239 cw(c73.918,29.132) 74.023,29.239 74.059,29.203 cw(c73.953,29.097) 74.059,28.991 ccw(c74.165,28.885) 74.059,28.779 74.094,28.744 ccw(c74.2,28.85) 74.306,28.744 cw(c74.412,28.638) 74.518,28.744 74.554,28.708 cw(c74.448,28.602) 74.554,28.496 ccw(c74.66,28.39) 74.554,28.284 74.589,28.249 ccw(c74.695,28.355) 74.801,28.249 cw(c74.907,28.143) 75.013,28.249 75.049,28.213 cw(c74.943,28.107) 75.049,28.001 ccw(c75.155,27.895) 75.049,27.789 75.084,27.754 ccw(c75.19,27.86) 75.296,27.754 cw(c75.402,27.648) 75.508,27.754 ; 75.508,27.754 75.544,27.718 ; 75.544,27.718 cw(c75.438,27.612) 75.544,27.506 ccw(c75.65,27.4) 75.544,27.294 75.579,27.259 ccw(c75.685,27.365) 75.791,27.259 cw(c75.897,27.153) 76.003,27.259 76.039,27.223 cw(c75.933,27.117) 76.039,27.011 ccw(c76.145,26.905) 76.039,26.799 76.074,26.764 ccw(c76.18,26.87) 76.286,26.764 cw(c76.392,26.658) 76.498,26.764 76.534,26.728 cw(c76.428,26.622) 76.534,26.516 ccw(c76.64,26.41) 76.534,26.304 76.569,26.269 ccw(c76.675,26.375) 76.781,26.269 cw(c76.887,26.163) 76.993,26.269 77.029,26.233 cw(c76.923,26.127) 77.029,26.021 ccw(c77.135,25.915) 77.029,25.809 ; 77.029,25.809 77.064,25.774 ; 77.064,25.774 ccw(c77.17,25.88) 77.276,25.774 77.575,25.475 78.618,25.475 cw(c78.618,25.352) 78.741,25.352 78.741,25.247 cw(c78.618,25.247) 78.618,25.125 78.082,25.125 ccw(c78.082,25.002) 77.959,25.002 77.959,24.897 ccw(c78.082,24.897) 78.082,24.775 78.618,24.775 cw(c78.618,24.652) 78.741,24.652 78.741,24.547 cw(c78.618,24.547) 78.618,24.425 78.082,24.425 ccw(c78.082,24.302) 77.959,24.302 77.959,24.197 ccw(c78.082,24.197) 78.082,24.075 78.618,24.075 cw(c78.618,23.952) 78.741,23.952 78.741,23.847 cw(c78.618,23.847) 78.618,23.725 78.082,23.725 ccw(c78.082,23.602) 77.959,23.602 77.959,23.497 ccw(c78.082,23.497) 78.082,23.375 78.618,23.375 cw(c78.618,23.252) 78.741,23.252 78.741,23.147 cw(c78.618,23.147) 78.618,23.025 78.082,23.025 ccw(c78.082,22.902) 77.959,22.902 77.959,22.797 ccw(c78.082,22.797) 78.082,22.675 78.618,22.675 cw(c78.618,22.552) 78.741,22.552 78.741,22.447 cw(c78.618,22.447) 78.618,22.325 78.082,22.325 ccw(c78.082,22.202) 77.959,22.202 77.959,22.097 ccw(c78.082,22.097) 78.082,21.975 78.618,21.975 cw(c78.618,21.852) 78.741,21.852 78.741,21.747 cw(c78.618,21.747) 78.618,21.625 78.082,21.625 ccw(c78.082,21.502) 77.959,21.502 77.959,21.397 ccw(c78.082,21.397) 78.082,21.275 78.618,21.275 cw(c78.618,21.152) 78.741,21.152 78.741,21.047 cw(c78.618,21.047) 78.618,20.925 78.082,20.925 ccw(c78.082,20.802) 77.959,20.802 77.959,20.697 ccw(c78.082,20.697) 78.082,20.575 78.618,20.575 cw(c78.618,20.452) 78.741,20.452 78.741,20.347 cw(c78.618,20.347) 78.618,20.225 78.082,20.225 ccw(c78.082,20.102) 77.959,20.102 77.959,19.997 ccw(c78.082,19.997) 78.082,19.875 78.618,19.875 cw(c78.618,19.752) 78.741,19.752 78.741,19.647 cw(c78.618,19.647) 78.618,19.525 78.082,19.525 ccw(c78.082,19.402) 77.959,19.402 77.959,19.297 ccw(c78.082,19.297) 78.082,19.175 78.618,19.175 cw(c78.618,19.052) 78.741,19.052 78.741,18.947 cw(c78.618,18.947) 78.618,18.825 78.082,18.825 ccw(c78.082,18.702) 77.959,18.702 77.959,18.597 ccw(c78.082,18.597) 78.082,18.475 78.618,18.475 cw(c78.618,18.352) 78.741,18.352 78.741,18.247 cw(c78.618,18.247) 78.618,18.125 78.082,18.125 ccw(c78.082,18.002) 77.959,18.002 77.959,17.897 ccw(c78.082,17.897) 78.082,17.775 78.227,17.775 cw(c78.227,17.652) 78.35,17.652 78.35,17.125 U11.100@78.075,17.125
RAM_A03: U8.B6 U11.99 | length 41.4
  Top Layer w0.15: U8.B6@71,37 71.05,37 71.5,36.55 71.5,34.6 ccw(c71.675,34.6) 71.675,34.425 cw(c71.675,34.25) 71.85,34.25 cw(c71.675,34.25) 71.675,34.075 ccw(c71.675,33.9) 71.5,33.9 ccw(c71.675,33.9) 71.675,33.725 cw(c71.675,33.55) 71.85,33.55 cw(c71.675,33.55) 71.675,33.375 ccw(c71.675,33.2) 71.5,33.2 71.5,32.85 71.747,32.603 cw(c71.624,32.479) 71.747,32.355 71.712,32.32 ccw(c71.836,32.196) 71.712,32.072 ccw(c71.836,32.196) 71.96,32.072 72.278,32.39 cw(c72.402,32.267) 72.525,32.39 cw(c72.402,32.267) 72.525,32.143 72.207,31.825 ccw(c72.331,31.701) 72.207,31.577 ccw(c72.331,31.701) 72.455,31.577 72.614,31.736 72.773,31.895 cw(c72.897,31.772) 73.02,31.895 cw(c72.897,31.772) 73.02,31.648 72.861,31.489 72.702,31.33 ccw(c72.826,31.206) 72.702,31.082 ccw(c72.826,31.206) 72.95,31.082 73.109,31.241 73.268,31.4 cw(c73.392,31.277) 73.515,31.4 cw(c73.392,31.277) 73.515,31.153 73.197,30.835 ccw(c73.321,30.711) 73.197,30.587 ccw(c73.321,30.711) 73.445,30.587 73.604,30.746 73.763,30.905 cw(c73.886,30.782) 74.01,30.905 cw(c73.886,30.782) 74.01,30.658 73.851,30.499 73.692,30.34 ccw(c73.816,30.216) 73.692,30.092 ccw(c73.816,30.216) 73.94,30.092 74.099,30.251 74.258,30.41 cw(c74.381,30.287) 74.505,30.41 cw(c74.381,30.287) 74.505,30.163 74.187,29.845 ccw(c74.311,29.721) 74.187,29.597 ccw(c74.311,29.721) 74.434,29.597 74.753,29.916 cw(c74.876,29.792) 75,29.916 cw(c74.876,29.792) 75,29.668 74.841,29.509 74.682,29.35 ccw(c74.806,29.226) 74.682,29.102 ccw(c74.806,29.226) 74.929,29.102 75.089,29.261 75.248,29.421 cw(c75.371,29.297) 75.495,29.421 cw(c75.371,29.297) 75.495,29.173 75.336,29.014 75.177,28.855 ccw(c75.301,28.731) 75.177,28.607 ccw(c75.301,28.731) 75.424,28.607 75.743,28.926 cw(c75.866,28.802) 75.99,28.926 cw(c75.866,28.802) 75.99,28.678 75.831,28.519 75.672,28.36 ccw(c75.796,28.236) 75.672,28.112 ccw(c75.796,28.236) 75.919,28.112 76.079,28.271 76.238,28.431 cw(c76.361,28.307) 76.485,28.431 cw(c76.361,28.307) 76.485,28.183 76.326,28.024 76.167,27.865 ccw(c76.291,27.741) 76.167,27.617 ccw(c76.291,27.741) 76.414,27.617 76.733,27.936 cw(c76.856,27.812) 76.98,27.936 cw(c76.856,27.812) 76.98,27.688 76.662,27.37 ccw(c76.786,27.246) 76.662,27.122 ccw(c76.786,27.246) 76.909,27.122 77.068,27.282 77.228,27.441 cw(c77.351,27.317) 77.475,27.441 cw(c77.351,27.317) 77.475,27.193 77.316,27.034 77.157,26.875 ccw(c77.281,26.751) 77.157,26.627 ccw(c77.281,26.751) 77.404,26.627 77.563,26.787 77.723,26.946 cw(c77.846,26.822) 77.97,26.946 cw(c77.846,26.822) 77.97,26.698 77.935,26.663 ccw(c78.058,26.539) 77.935,26.415 78.1,26.25 78.45,26.25 79.2,25.5 79.2,16.65 79.025,16.475 U11.99@78.075,16.475
RAM_A04: U8.D3 U11.83 | length 40.9
  Top Layer w0.15: U8.D3@74,39 74.5,38.5 75.15,38.5 cw(c75.325,38.397) 75.5,38.5 ccw(c75.675,38.603) 75.85,38.5 77.05,38.5 78.829,36.721 ccw(c78.9,36.65) 78.829,36.58 78.935,36.474 ccw(c79.006,36.544) 79.076,36.474 79.324,36.226 ccw(c79.395,36.155) 79.324,36.085 79.43,35.979 ccw(c79.501,36.049) 79.571,35.979 79.819,35.731 ccw(c79.89,35.66) 79.819,35.59 79.925,35.484 ccw(c79.996,35.554) 80.066,35.484 80.314,35.236 ccw(c80.385,35.165) 80.314,35.095 80.42,34.989 ccw(c80.491,35.059) 80.561,34.989 80.809,34.741 ccw(c80.88,34.67) 80.809,34.6 80.915,34.494 ccw(c80.986,34.564) 81.056,34.494 81.304,34.246 ccw(c81.374,34.176) 81.304,34.105 81.41,33.999 ccw(c81.481,34.069) 81.551,33.999 81.95,33.6 81.95,8.8 81.141,7.991 ccw(c81.322,7.492) 80.823,7.673 cw(c80.323,7.854) 80.505,7.355 ccw(c80.686,6.855) 80.186,7.036 cw(c79.687,7.218) 79.868,6.718 ccw(c80.049,6.219) 79.55,6.4 79.225,6.075 U11.83@78.075,6.075
RAM_A05: U8.D1 U11.82 | length 40.9
  Top Layer w0.15: U8.D1@76,39 77.1,39 77.495,38.605 cw(c77.546,38.408) 77.743,38.357 ccw(c77.939,38.306) 77.99,38.11 cw(c78.041,37.913) 78.238,37.862 ccw(c78.434,37.811) 78.485,37.615 cw(c78.536,37.418) 78.733,37.367 ccw(c78.929,37.316) 78.98,37.12 cw(c79.031,36.923) 79.228,36.872 ccw(c79.424,36.822) 79.475,36.625 cw(c79.526,36.428) 79.723,36.377 ccw(c79.919,36.327) 79.97,36.13 cw(c80.021,35.933) 80.218,35.882 ccw(c80.414,35.832) 80.465,35.635 cw(c80.516,35.438) 80.713,35.387 ccw(c80.909,35.337) 80.96,35.14 cw(c81.011,34.943) 81.208,34.892 ccw(c81.404,34.842) 81.455,34.645 cw(c81.506,34.448) 81.703,34.397 ccw(c81.899,34.347) 81.95,34.15 82.2,33.9 82.2,8.4 81.921,8.121 cw(c81.618,8.105) 81.602,7.802 ccw(c81.587,7.5) 81.284,7.484 cw(c80.981,7.469) 80.966,7.166 ccw(c80.951,6.863) 80.648,6.848 cw(c80.345,6.832) 80.33,6.53 ccw(c80.314,6.227) 80.011,6.211 cw(c79.709,6.196) 79.693,5.893 79.225,5.425 U11.82@78.075,5.425
RAM_A06: U8.D2 U11.81 | length 41.8
  Top Layer w0.15: U8.D2@75,39 75.004,39 75.504,39.5 77.3,39.5 82.45,34.35 82.45,8.1 79.125,4.775 U11.81@78.075,4.775
RAM_A07: U8.B18 U11.50 | length 41.2
  Top Layer w0.15: U11.50@56.825,4.775 55.725,4.775 53,7.5 53,11.25 50.85,13.4 50.85,31.6 52.628,33.378 cw(c52.769,33.519) 52.628,33.661 52.734,33.767 cw(c52.875,33.625) 53.017,33.767 53.95,34.7 57.866,34.7 58.5,35.334 58.5,36.5 U8.B18@59,37
RAM_A08: U8.A18 U11.49 | length 40.7
  Top Layer w0.15: U11.49@56.825,5.425 55.825,5.425 53.35,7.9 53.35,11.3 51.25,13.4 51.25,23.9 cw(c51.427,24.175) 51.25,24.45 51.25,25 cw(c51.427,25.275) 51.25,25.55 51.25,26.1 cw(c51.427,26.375) 51.25,26.65 51.25,27.2 cw(c51.427,27.475) 51.25,27.75 51.25,28.3 cw(c51.427,28.575) 51.25,28.85 51.25,29.4 cw(c51.427,29.675) 51.25,29.95 51.25,31.3 51.556,31.606 cw(c51.627,31.677) 51.556,31.747 51.627,31.818 cw(c51.697,31.747) 51.768,31.818 ccw(c51.839,31.889) 51.91,31.818 51.98,31.889 ccw(c51.91,31.96) 51.98,32.03 cw(c52.051,32.101) 51.98,32.172 52.051,32.242 cw(c52.122,32.172) 52.192,32.242 ccw(c52.263,32.313) 52.334,32.242 52.405,32.313 ccw(c52.334,32.384) 52.405,32.455 cw(c52.475,32.525) 52.405,32.596 52.475,32.667 cw(c52.546,32.596) 52.617,32.667 ccw(c52.687,32.737) 52.758,32.667 52.829,32.737 ccw(c52.758,32.808) 52.829,32.879 cw(c52.9,32.95) 52.829,33.02 52.9,33.091 cw(c52.97,33.02) 53.041,33.091 ccw(c53.112,33.162) 53.182,33.091 53.253,33.162 ccw(c53.182,33.232) 53.253,33.303 cw(c53.324,33.374) 53.253,33.445 53.324,33.515 cw(c53.395,33.445) 53.465,33.515 ccw(c53.536,33.586) 53.607,33.515 53.677,33.586 ccw(c53.607,33.657) 53.677,33.727 cw(c53.748,33.798) 53.677,33.869 53.748,33.94 cw(c53.819,33.869) 53.89,33.94 54.4,34.45 58.05,34.45 59,35.4 U8.A18@59,36
RAM_A09: U8.C17 U11.48 | length 40.8
  Top Layer w0.15: U11.48@56.825,6.075 55.725,6.075 53.65,8.15 53.65,11.45 51.6,13.5 51.6,31.05 54.55,34 55.15,34 cw(c55.425,33.823) 55.7,34 ccw(c55.975,34.177) 56.25,34 cw(c56.525,33.823) 56.8,34 ccw(c57.075,34.177) 57.35,34 cw(c57.625,33.823) 57.9,34 58.1,34 59.5,35.4 59.5,37.5 U8.C17@60,38
RAM_A10: U8.A17 U11.47 | length 41
  Top Layer w0.15: 52.199,31.082 ccw(c52.284,30.997) 52.199,30.913 cw(c52.143,30.856) 52.199,30.799 51.9,30.5 51.9,13.65 53.95,11.6 53.95,8.45 55.675,6.725 U11.47@56.825,6.725 ; 52.199,31.082 52.242,31.125 cw(c52.327,31.04) 52.411,31.125 52.468,31.068 52.525,31.012 ccw(c52.61,31.096) 52.694,31.011 52.737,31.054 ccw(c52.652,31.139) 52.737,31.224 52.624,31.337 cw(c52.709,31.422) 52.624,31.506 ; 52.624,31.507 52.666,31.549 cw(c52.751,31.464) 52.836,31.549 52.892,31.492 52.949,31.436 ccw(c53.034,31.521) 53.119,31.436 53.161,31.478 ccw(c53.076,31.563) 53.161,31.648 53.105,31.705 53.048,31.761 cw(c53.133,31.846) 53.048,31.931 53.09,31.973 cw(c53.175,31.888) 53.26,31.973 53.317,31.917 53.373,31.86 ccw(c53.458,31.945) 53.543,31.86 53.585,31.903 ccw(c53.501,31.987) 53.585,32.072 53.529,32.129 53.472,32.185 cw(c53.557,32.27) 53.472,32.355 53.515,32.398 cw(c53.6,32.313) 53.684,32.398 53.741,32.341 53.798,32.284 ccw(c53.882,32.369) 53.967,32.284 54.01,32.327 ; 54.01,32.327 ccw(c53.925,32.412) 54.01,32.497 53.953,32.553 53.897,32.61 cw(c53.981,32.695) 53.896,32.779 53.939,32.822 cw(c54.024,32.737) 54.109,32.822 54.165,32.765 54.222,32.709 ccw(c54.307,32.794) 54.391,32.709 54.434,32.751 ; 54.434,32.751 ccw(c54.349,32.836) 54.434,32.921 cw(c54.491,32.977) 54.434,33.034 54.95,33.55 58.4,33.55 58.563,33.713 cw(c58.705,33.817) 58.81,33.96 ccw(c58.915,34.103) 59.058,34.208 cw(c59.2,34.312) 59.305,34.455 ccw(c59.41,34.598) 59.553,34.703 cw(c59.695,34.807) 59.8,34.95 60,35.15 U8.A17@60,36
RAM_A11: U8.B16 U11.46 | length 40.9
  Top Layer w0.15: 52.702,30.059 52.659,30.102 ccw(c52.574,30.017) 52.49,30.102 52.447,30.059 ccw(c52.532,29.974) 52.447,29.889 cw(c52.426,29.868) 52.447,29.847 52.15,29.55 52.15,13.85 54.25,11.75 54.25,8.8 55.675,7.375 U11.46@56.825,7.375 ; 52.702,30.059 ccw(c52.786,30.144) 52.871,30.059 52.914,30.102 ; 52.914,30.526 52.871,30.483 ccw(c52.956,30.399) 52.871,30.314 52.914,30.271 cw(c52.829,30.186) 52.914,30.102 ; 52.914,30.526 cw(c52.999,30.441) 53.083,30.526 53.126,30.483 ccw(c53.211,30.568) 53.295,30.483 53.338,30.526 ccw(c53.253,30.611) 53.338,30.695 ; 53.338,30.696 53.296,30.738 cw(c53.38,30.823) 53.295,30.907 53.338,30.95 cw(c53.423,30.865) 53.507,30.95 53.529,30.929 53.55,30.908 ccw(c53.635,30.992) 53.72,30.908 53.762,30.95 ccw(c53.677,31.035) 53.762,31.12 53.72,31.162 cw(c53.805,31.247) 53.72,31.332 53.762,31.374 ; 53.762,31.374 cw(c53.847,31.289) 53.932,31.374 53.974,31.332 ccw(c54.059,31.417) 54.144,31.332 54.186,31.374 ccw(c54.102,31.459) 54.186,31.544 54.144,31.586 cw(c54.229,31.671) 54.144,31.756 54.186,31.799 cw(c54.271,31.714) 54.356,31.799 ; 54.356,31.799 54.399,31.756 ccw(c54.483,31.841) 54.568,31.756 54.611,31.799 ; 54.611,31.799 ccw(c54.526,31.883) 54.611,31.968 54.568,32.011 cw(c54.653,32.096) 54.568,32.18 54.611,32.223 cw(c54.696,32.138) 54.78,32.223 54.823,32.18 ccw(c54.908,32.265) 54.992,32.18 55.035,32.223 ccw(c54.95,32.308) 55.035,32.393 54.993,32.435 cw(c55.077,32.52) 54.992,32.605 55.035,32.647 cw(c55.12,32.562) 55.205,32.647 55.226,32.626 55.247,32.605 ccw(c55.332,32.69) 55.417,32.605 55.459,32.647 ccw(c55.374,32.732) 55.459,32.817 cw(c55.48,32.838) 55.459,32.859 55.9,33.3 58.9,33.3 59.386,33.786 59.379,33.793 cw(c59.478,33.892) 59.379,33.991 59.429,34.041 cw(c59.528,33.942) 59.627,34.041 59.634,34.034 59.881,34.281 59.874,34.288 cw(c59.973,34.387) 59.874,34.486 59.924,34.536 cw(c60.023,34.437) 60.122,34.536 60.129,34.529 60.5,34.9 60.5,35.175 60.49,35.175 cw(c60.49,35.315) 60.35,35.315 60.35,35.385 cw(c60.49,35.385) 60.49,35.525 60.5,35.525 60.5,36.5 U8.B16@61,37
RAM_A12: U8.A16 U11.45 | length 40.8
  Top Layer w0.15: 53.269,29.236 cw(c53.185,29.321) 53.1,29.237 53.043,29.293 52.987,29.35 ccw(c52.902,29.265) 52.817,29.35 52.774,29.307 ccw(c52.859,29.222) 52.774,29.138 cw(c52.718,29.081) 52.774,29.024 52.45,28.7 52.45,13.95 54.55,11.85 54.55,9 55.525,8.025 U11.45@56.825,8.025 ; 53.269,29.237 53.312,29.279 ccw(c53.227,29.364) 53.312,29.449 53.199,29.562 cw(c53.284,29.647) 53.199,29.731 53.241,29.774 cw(c53.326,29.689) 53.411,29.774 53.467,29.717 53.524,29.661 ccw(c53.609,29.746) 53.694,29.661 53.736,29.703 ccw(c53.651,29.788) 53.736,29.873 53.68,29.93 53.623,29.986 cw(c53.708,30.071) 53.623,30.156 53.665,30.198 ; 53.666,30.198 cw(c53.75,30.113) 53.835,30.198 53.892,30.142 53.948,30.085 ccw(c54.033,30.17) 54.118,30.085 54.16,30.128 ccw(c54.076,30.212) 54.16,30.297 54.104,30.354 54.047,30.41 ; 54.047,30.411 cw(c54.132,30.495) 54.047,30.58 54.09,30.623 ; 54.09,30.623 cw(c54.175,30.538) 54.259,30.623 54.316,30.566 54.373,30.509 ccw(c54.457,30.594) 54.542,30.509 54.585,30.552 ccw(c54.5,30.637) 54.585,30.722 54.528,30.778 54.472,30.835 cw(c54.556,30.92) 54.471,31.004 54.514,31.047 ; 54.514,31.047 cw(c54.599,30.962) 54.684,31.047 54.74,30.99 54.797,30.934 ccw(c54.882,31.019) 54.966,30.934 55.009,30.976 ccw(c54.924,31.061) 55.009,31.146 54.896,31.259 cw(c54.981,31.344) 54.896,31.429 54.938,31.471 cw(c55.023,31.386) 55.108,31.471 55.165,31.415 55.221,31.358 ccw(c55.306,31.443) 55.391,31.358 ; 55.391,31.358 55.433,31.4 ccw(c55.348,31.485) 55.433,31.57 55.377,31.627 55.32,31.683 cw(c55.405,31.768) 55.32,31.853 55.362,31.895 cw(c55.447,31.81) 55.532,31.895 55.589,31.839 55.645,31.782 ccw(c55.73,31.867) 55.815,31.782 ; 55.815,31.782 55.857,31.825 ccw(c55.773,31.909) 55.858,31.994 ; 55.857,31.994 55.801,32.051 55.744,32.107 cw(c55.829,32.192) 55.744,32.277 55.787,32.32 cw(c55.872,32.235) 55.956,32.32 56.013,32.263 56.07,32.206 ccw(c56.154,32.291) 56.239,32.206 56.282,32.249 ; 56.282,32.249 ccw(c56.197,32.334) 56.282,32.419 cw(c56.338,32.475) 56.282,32.532 56.65,32.9 57.175,32.9 57.175,32.91 cw(c57.315,32.91) 57.315,33.05 57.385,33.05 cw(c57.385,32.91) 57.525,32.91 57.525,32.89 ccw(c57.665,32.89) 57.665,32.75 57.735,32.75 ccw(c57.735,32.89) 57.875,32.89 57.875,32.91 cw(c58.015,32.91) 58.015,33.05 58.085,33.05 cw(c58.085,32.91) 58.225,32.91 58.225,32.89 ccw(c58.365,32.89) 58.365,32.75 58.435,32.75 ccw(c58.435,32.89) 58.575,32.89 58.575,32.9 58.904,32.9 61,34.996 U8.A16@61,36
